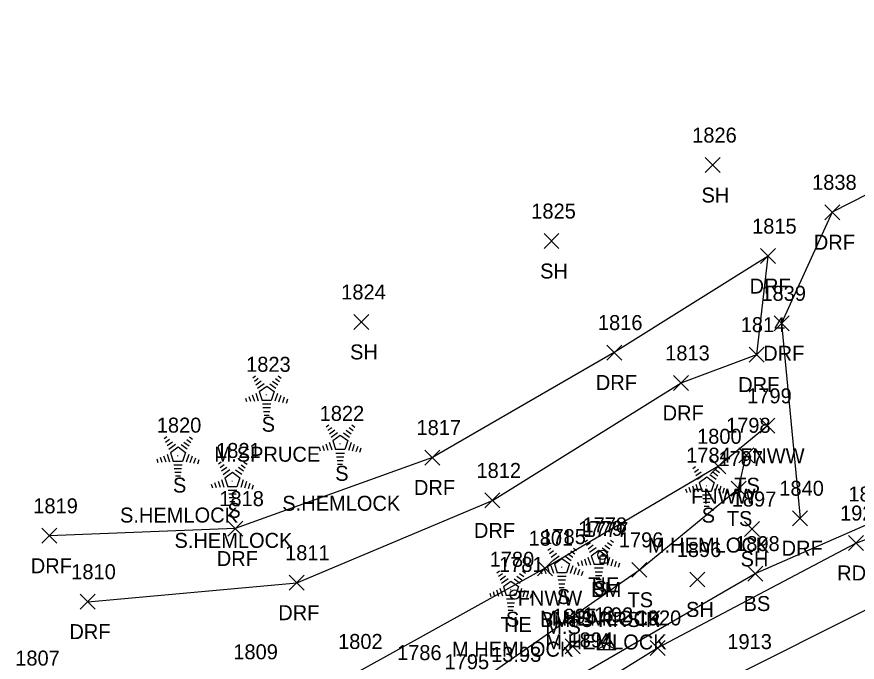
# Model space of a CAD drawing. Extents: x 1621633 to 1624015, y 417863 to 420979.
# Drawn here: x 1621653.9 to 1621766.2, y 418036.6 to 418122.7 of the extents above; entities that cross this region are included whole.
import ezdxf

# ---------------------------------------------------------------- set-up
doc = ezdxf.new("R2010")
doc.units = 0
for name, color, linetype in [('C_A', 7, 'Continuous'), ('C_C', 7, 'Continuous'), ('C_I', 7, 'Continuous'), ('CBP', 7, 'Continuous'), ('CPBM', 7, 'Continuous'), ('CPSM', 7, 'Continuous'), ('L_A', 7, 'Continuous'), ('L_C', 7, 'Continuous'), ('L_I', 7, 'Continuous'), ('L_TIC', 7, 'Continuous'), ('LELB', 7, 'Continuous'), ('LFNC', 7, 'Continuous'), ('LTC', 7, 'Continuous'), ('P_A', 7, 'Continuous'), ('P_I', 7, 'Continuous'), ('P_TIC', 7, 'Continuous'), ('PEU', 7, 'Continuous'), ('PRC', 7, 'Continuous'), ('R_A', 7, 'Continuous'), ('R_I', 7, 'Continuous'), ('R_TIC', 7, 'Continuous'), ('RDF', 7, 'Continuous')]:
    doc.layers.add(name, color=color, linetype=linetype)

msp = doc.modelspace()

# ---------------------------------------------------------------- linework, layer by layer
at = {"layer": 'CBP'}
for centre, radius in [((1621732.16, 418050.87), 0.625), ((1621732.16, 418050.87), 0.0833), ((1621720.46, 418045.6), 0.625), ((1621720.46, 418045.6), 0.0833)]:
    msp.add_circle(centre, radius, dxfattribs=at)
at = {"layer": 'CPBM'}
for p, q in [((1621731.83, 418049.75), (1621731.83, 418050.75)), ((1621731.83, 418050.75), (1621732.83, 418050.75)), ((1621732.83, 418050.75), (1621732.83, 418049.75)), ((1621732.83, 418049.75), (1621731.83, 418049.75)), ((1621732.33, 418050.25), (1621732.33, 418050.25)), ((1621732.33, 418050.25), (1621732.33, 418050.25))]:
    msp.add_line(p, q, dxfattribs=at)
at = {"layer": 'CPSM'}
for p, q in [((1621731.45, 418038.24), (1621732.7, 418040.4)), ((1621733.95, 418038.24), (1621732.7, 418040.4)), ((1621732.7, 418038.96), (1621732.7, 418040.4)), ((1621731.45, 418038.24), (1621732.7, 418038.96)), ((1621731.45, 418038.24), (1621733.95, 418038.24)), ((1621732.7, 418038.96), (1621732.7, 418038.96)), ((1621732.7, 418038.96), (1621733.95, 418038.24))]:
    msp.add_line(p, q, dxfattribs=at)
at = {"layer": 'L_TIC'}
for points in [[(1621745.88, 418101.9), (1621747.88, 418103.9)], [(1621747.88, 418101.9), (1621745.88, 418103.9)], [(1621724.34, 418091.76), (1621726.34, 418093.76)], [(1621726.34, 418091.76), (1621724.34, 418093.76)], [(1621698.95, 418080.96), (1621700.95, 418082.96)], [(1621700.95, 418080.96), (1621698.95, 418082.96)], [(1621753.17, 418067.1), (1621755.17, 418069.1)], [(1621755.17, 418067.1), (1621753.17, 418069.1)], [(1621750.34, 418063.17), (1621752.34, 418065.17)], [(1621752.34, 418063.17), (1621750.34, 418065.17)], [(1621746.63, 418061.7), (1621748.63, 418063.7)], [(1621748.63, 418061.7), (1621746.63, 418063.7)], [(1621749.33, 418058.72), (1621751.33, 418060.72)], [(1621751.33, 418058.72), (1621749.33, 418060.72)], [(1621751.11, 418053.33), (1621753.11, 418055.33)], [(1621753.11, 418053.33), (1621751.11, 418055.33)], [(1621723.49, 418048.1), (1621725.49, 418050.1)], [(1621725.49, 418048.1), (1621723.49, 418050.1)], [(1621736.08, 418047.88), (1621738.08, 418049.88)], [(1621738.08, 418047.88), (1621736.08, 418049.88)], [(1621751.55, 418047.38), (1621753.55, 418049.38)], [(1621753.55, 418047.38), (1621751.55, 418049.38)], [(1621743.81, 418046.59), (1621745.81, 418048.59)], [(1621745.81, 418046.59), (1621743.81, 418048.59)], [(1621727.15, 418037.69), (1621729.15, 418039.69)], [(1621729.15, 418037.69), (1621727.15, 418039.69)]]:
    msp.add_lwpolyline(points, dxfattribs=at)
at = {"layer": 'LELB'}
for points in [[(1621664.03, 417989.43), (1621687.49, 418007.66), (1621711.94, 418024.27), (1621730.31, 418035.53), (1621752.55, 418048.38), (1621767.69, 418055), (1621798.3, 418066.25), (1621826.91, 418075.93), (1621858.25, 418085.3), (1621888.98, 418092.53), (1621914.26, 418098.41), (1621931, 418100.47)], [(1621661.36, 417992.68), (1621685.31, 418010.41), (1621692.18, 418016.19), (1621713.76, 418032.62), (1621737.08, 418048.88), (1621750.33, 418059.72), (1621751.34, 418064.17)]]:
    msp.add_lwpolyline(points, dxfattribs=at)
at = {"layer": 'LFNC'}
msp.add_lwpolyline([(1621754.17, 418068.1), (1621747.63, 418062.7), (1621724.49, 418049.1), (1621699.62, 418035.32), (1621679.62, 418023.17), (1621653.98, 418003.68)], dxfattribs=at)
at = {"layer": 'LTC'}
for p, q in [((1621685.45, 418074.52), (1621685.8, 418074.78)), ((1621685.66, 418074.06), (1621686.19, 418074.44)), ((1621685.87, 418073.59), (1621686.57, 418074.1)), ((1621688.1, 418074.07), (1621688.78, 418073.57)), ((1621688.47, 418074.41), (1621689.02, 418074.02)), ((1621688.85, 418074.76), (1621689.26, 418074.46)), ((1621686.08, 418073.13), (1621686.95, 418073.76)), ((1621686.3, 418072.67), (1621687.31, 418073.41)), ((1621687.31, 418073.41), (1621688.31, 418072.68)), ((1621687.73, 418073.72), (1621688.54, 418073.13)), ((1621684.48, 418071.8), (1621684.63, 418071.33)), ((1621684.94, 418072.02), (1621685.15, 418071.37)), ((1621685.39, 418072.24), (1621685.66, 418071.4)), ((1621685.85, 418072.45), (1621686.18, 418071.43)), ((1621686.3, 418072.67), (1621686.69, 418071.48)), ((1621688.31, 418072.68), (1621687.92, 418071.48)), ((1621688.75, 418072.41), (1621688.41, 418071.37)), ((1621689.19, 418072.16), (1621688.9, 418071.27)), ((1621689.64, 418071.91), (1621689.4, 418071.18)), ((1621687.92, 418071.48), (1621686.69, 418071.48)), ((1621687.88, 418070.98), (1621686.74, 418070.98)), ((1621690.08, 418071.66), (1621689.89, 418071.08)), ((1621687.8, 418070.48), (1621686.81, 418070.48)), ((1621687.71, 418069.98), (1621686.88, 418069.98)), ((1621687.63, 418069.48), (1621686.95, 418069.48)), ((1621695.27, 418067.97), (1621695.62, 418068.23)), ((1621695.48, 418067.5), (1621696.01, 418067.89)), ((1621695.69, 418067.04), (1621696.39, 418067.55)), ((1621695.9, 418066.57), (1621696.78, 418067.21)), ((1621697.92, 418067.51), (1621698.6, 418067.02)), ((1621698.3, 418067.86), (1621698.85, 418067.46)), ((1621698.67, 418068.21), (1621699.09, 418067.91)), ((1621673.6, 418066.4), (1621673.96, 418066.66)), ((1621673.81, 418065.94), (1621674.34, 418066.32)), ((1621676.63, 418066.29), (1621677.18, 418065.89)), ((1621677, 418066.64), (1621677.42, 418066.34)), ((1621696.12, 418066.12), (1621697.13, 418066.85)), ((1621696.12, 418066.12), (1621696.51, 418064.92)), ((1621697.13, 418066.85), (1621698.13, 418066.13)), ((1621697.55, 418067.17), (1621698.36, 418066.58)), ((1621698.13, 418066.13), (1621697.74, 418064.92)), ((1621674.02, 418065.47), (1621674.72, 418065.98)), ((1621674.23, 418065), (1621675.11, 418065.64)), ((1621674.45, 418064.55), (1621675.47, 418065.28)), ((1621675.47, 418065.28), (1621676.46, 418064.56)), ((1621675.89, 418065.6), (1621676.7, 418065.01)), ((1621676.26, 418065.94), (1621676.94, 418065.45)), ((1621694.3, 418065.25), (1621694.45, 418064.78)), ((1621694.76, 418065.47), (1621694.97, 418064.81)), ((1621695.21, 418065.68), (1621695.48, 418064.85)), ((1621695.67, 418065.9), (1621696, 418064.88)), ((1621698.57, 418065.86), (1621698.23, 418064.82)), ((1621699.01, 418065.61), (1621698.73, 418064.72)), ((1621699.46, 418065.36), (1621699.22, 418064.63)), ((1621699.9, 418065.11), (1621699.71, 418064.53)), ((1621673.09, 418063.9), (1621673.3, 418063.25)), ((1621673.54, 418064.11), (1621673.82, 418063.28)), ((1621674, 418064.33), (1621674.33, 418063.31)), ((1621674.45, 418064.55), (1621674.84, 418063.36)), ((1621676.46, 418064.56), (1621676.07, 418063.36)), ((1621676.9, 418064.29), (1621676.56, 418063.25)), ((1621677.34, 418064.04), (1621677.06, 418063.15)), ((1621697.74, 418064.92), (1621696.51, 418064.92)), ((1621697.7, 418064.42), (1621696.56, 418064.42)), ((1621697.62, 418063.92), (1621696.63, 418063.92)), ((1621672.63, 418063.68), (1621672.79, 418063.21)), ((1621676.07, 418063.36), (1621674.84, 418063.36)), ((1621676.03, 418062.86), (1621674.89, 418062.86)), ((1621677.79, 418063.79), (1621677.55, 418063.06)), ((1621678.23, 418063.54), (1621678.05, 418062.96)), ((1621680.87, 418063.02), (1621681.23, 418063.28)), ((1621681.08, 418062.55), (1621681.61, 418062.94)), ((1621683.9, 418062.91), (1621684.45, 418062.51)), ((1621684.27, 418063.26), (1621684.69, 418062.96)), ((1621697.53, 418063.42), (1621696.7, 418063.42)), ((1621697.45, 418062.92), (1621696.77, 418062.92)), ((1621675.95, 418062.36), (1621674.96, 418062.36)), ((1621675.87, 418061.86), (1621675.03, 418061.86)), ((1621681.29, 418062.09), (1621682, 418062.6)), ((1621681.5, 418061.62), (1621682.38, 418062.26)), ((1621681.73, 418061.17), (1621682.74, 418061.9)), ((1621682.74, 418061.9), (1621683.74, 418061.18)), ((1621683.16, 418062.22), (1621683.97, 418061.63)), ((1621683.53, 418062.56), (1621684.21, 418062.07)), ((1621744.21, 418062.39), (1621744.57, 418062.65)), ((1621744.42, 418061.93), (1621744.95, 418062.31)), ((1621744.63, 418061.46), (1621745.34, 418061.97)), ((1621744.84, 418061), (1621745.72, 418061.63)), ((1621746.87, 418061.94), (1621747.55, 418061.44)), ((1621747.24, 418062.28), (1621747.79, 418061.89)), ((1621747.61, 418062.63), (1621748.03, 418062.33)), ((1621675.78, 418061.36), (1621675.11, 418061.36)), ((1621680.36, 418060.52), (1621680.57, 418059.86)), ((1621680.82, 418060.73), (1621681.09, 418059.9)), ((1621681.27, 418060.95), (1621681.6, 418059.93)), ((1621681.73, 418061.17), (1621682.11, 418059.97)), ((1621683.74, 418061.18), (1621683.34, 418059.97)), ((1621684.17, 418060.91), (1621683.84, 418059.87)), ((1621684.62, 418060.66), (1621684.33, 418059.77)), ((1621745.07, 418060.54), (1621746.08, 418061.28)), ((1621745.07, 418060.54), (1621745.45, 418059.35)), ((1621746.08, 418061.28), (1621747.08, 418060.55)), ((1621746.5, 418061.59), (1621747.31, 418061)), ((1621747.08, 418060.55), (1621746.68, 418059.35)), ((1621679.91, 418060.3), (1621680.06, 418059.83)), ((1621683.34, 418059.97), (1621682.11, 418059.97)), ((1621683.31, 418059.47), (1621682.16, 418059.47)), ((1621685.06, 418060.41), (1621684.83, 418059.68)), ((1621685.51, 418060.16), (1621685.32, 418059.58)), ((1621743.25, 418059.67), (1621743.4, 418059.2)), ((1621743.7, 418059.89), (1621743.91, 418059.24)), ((1621744.16, 418060.11), (1621744.43, 418059.27)), ((1621744.61, 418060.32), (1621744.94, 418059.3)), ((1621746.68, 418059.35), (1621745.45, 418059.35)), ((1621747.51, 418060.28), (1621747.17, 418059.24)), ((1621747.96, 418060.03), (1621747.67, 418059.14)), ((1621748.4, 418059.78), (1621748.16, 418059.05)), ((1621748.85, 418059.53), (1621748.66, 418058.95)), ((1621683.22, 418058.97), (1621682.23, 418058.97)), ((1621683.14, 418058.47), (1621682.31, 418058.47)), ((1621746.65, 418058.85), (1621745.5, 418058.85)), ((1621746.56, 418058.35), (1621745.57, 418058.35)), ((1621683.06, 418057.97), (1621682.38, 418057.97)), ((1621746.48, 418057.85), (1621745.65, 418057.85)), ((1621746.39, 418057.35), (1621745.72, 418057.35)), ((1621729.8, 418052.62), (1621730.16, 418052.88)), ((1621733.2, 418052.86), (1621733.62, 418052.56)), ((1621724.87, 418051.52), (1621725.23, 418051.78)), ((1621728.27, 418051.76), (1621728.69, 418051.46)), ((1621730.01, 418052.16), (1621730.54, 418052.54)), ((1621730.22, 418051.69), (1621730.92, 418052.2)), ((1621730.43, 418051.22), (1621731.31, 418051.86)), ((1621730.65, 418050.77), (1621731.67, 418051.5)), ((1621731.67, 418051.5), (1621732.66, 418050.78)), ((1621732.09, 418051.82), (1621732.9, 418051.23)), ((1621732.46, 418052.16), (1621733.14, 418051.67)), ((1621732.83, 418052.51), (1621733.38, 418052.11)), ((1621725.08, 418051.06), (1621725.61, 418051.44)), ((1621725.29, 418050.59), (1621726, 418051.1)), ((1621725.5, 418050.12), (1621726.38, 418050.76)), ((1621725.73, 418049.67), (1621726.74, 418050.4)), ((1621726.74, 418050.4), (1621727.73, 418049.68)), ((1621727.16, 418050.72), (1621727.97, 418050.13)), ((1621727.53, 418051.06), (1621728.21, 418050.57)), ((1621727.9, 418051.41), (1621728.45, 418051.01)), ((1621730.2, 418050.55), (1621730.53, 418049.53)), ((1621730.65, 418050.77), (1621731.04, 418049.58)), ((1621732.66, 418050.78), (1621732.27, 418049.58)), ((1621733.1, 418050.51), (1621732.76, 418049.47)), ((1621725.27, 418049.45), (1621725.6, 418048.43)), ((1621725.73, 418049.67), (1621726.11, 418048.48)), ((1621727.73, 418049.68), (1621727.34, 418048.48)), ((1621728.17, 418049.41), (1621727.83, 418048.37)), ((1621728.83, 418049.9), (1621728.99, 418049.43)), ((1621729.29, 418050.12), (1621729.5, 418049.47)), ((1621729.74, 418050.33), (1621730.02, 418049.5)), ((1621732.27, 418049.58), (1621731.04, 418049.58)), ((1621733.55, 418050.26), (1621733.26, 418049.37)), ((1621733.99, 418050.01), (1621733.75, 418049.28)), ((1621734.43, 418049.76), (1621734.25, 418049.18)), ((1621718.05, 418048.49), (1621718.41, 418048.75)), ((1621718.26, 418048.03), (1621718.79, 418048.41)), ((1621721.08, 418048.39), (1621721.63, 418047.99)), ((1621721.45, 418048.73), (1621721.87, 418048.43)), ((1621723.9, 418048.8), (1621724.06, 418048.33)), ((1621724.36, 418049.02), (1621724.57, 418048.37)), ((1621724.82, 418049.23), (1621725.09, 418048.4)), ((1621727.34, 418048.48), (1621726.11, 418048.48)), ((1621728.62, 418049.16), (1621728.33, 418048.27)), ((1621729.06, 418048.91), (1621728.82, 418048.18)), ((1621729.51, 418048.66), (1621729.32, 418048.08)), ((1621732.23, 418049.08), (1621731.09, 418049.08)), ((1621732.15, 418048.58), (1621731.16, 418048.58)), ((1621718.47, 418047.56), (1621719.18, 418048.07)), ((1621718.68, 418047.1), (1621719.56, 418047.74)), ((1621718.91, 418046.64), (1621719.92, 418047.38)), ((1621719.92, 418047.38), (1621720.92, 418046.65)), ((1621720.34, 418047.69), (1621721.15, 418047.1)), ((1621720.71, 418048.04), (1621721.39, 418047.54)), ((1621727.3, 418047.98), (1621726.16, 418047.98)), ((1621727.22, 418047.48), (1621726.23, 418047.48)), ((1621732.07, 418048.08), (1621731.23, 418048.08)), ((1621731.98, 418047.58), (1621731.31, 418047.58)), ((1621717.54, 418045.99), (1621717.75, 418045.34)), ((1621718, 418046.21), (1621718.27, 418045.37)), ((1621718.45, 418046.42), (1621718.78, 418045.4)), ((1621718.91, 418046.64), (1621719.3, 418045.45)), ((1621720.92, 418046.65), (1621720.53, 418045.45)), ((1621721.35, 418046.38), (1621721.02, 418045.34)), ((1621721.8, 418046.13), (1621721.51, 418045.25)), ((1621722.24, 418045.88), (1621722.01, 418045.15)), ((1621727.14, 418046.98), (1621726.31, 418046.98)), ((1621727.05, 418046.48), (1621726.38, 418046.48)), ((1621717.09, 418045.77), (1621717.24, 418045.31)), ((1621720.53, 418045.45), (1621719.3, 418045.45)), ((1621720.49, 418044.95), (1621719.34, 418044.95)), ((1621722.69, 418045.63), (1621722.5, 418045.06)), ((1621720.4, 418044.45), (1621719.42, 418044.45)), ((1621720.32, 418043.95), (1621719.49, 418043.95)), ((1621720.24, 418043.45), (1621719.56, 418043.45))]:
    msp.add_line(p, q, dxfattribs=at)
at = {"layer": 'P_TIC'}
for points in [[(1621765, 418051.46), (1621767, 418053.46)], [(1621767, 418051.46), (1621765, 418053.46)], [(1621738.5, 418037.46), (1621740.5, 418039.46)], [(1621740.5, 418037.46), (1621738.5, 418039.46)]]:
    msp.add_lwpolyline(points, dxfattribs=at)
at = {"layer": 'PEU'}
msp.add_lwpolyline([(1621666.09, 417987.33), (1621690.6, 418006.33), (1621714.11, 418022.73), (1621739.5, 418038.46), (1621766, 418052.46), (1621797.99, 418064.45), (1621829.1, 418075.2), (1621862.24, 418084.7), (1621894.03, 418092.42)], dxfattribs=at)
at = {"layer": 'PRC'}
msp.add_lwpolyline([(1621971.07, 418099.34), (1621938.44, 418093.73), (1621906.63, 418086.95), (1621874.87, 418079.94), (1621842.52, 418071.19), (1621811.53, 418061.42), (1621780.51, 418050.11), (1621750.95, 418035.3), (1621723.04, 418018.53), (1621696.18, 418000.53), (1621670.93, 417981.57)], dxfattribs=at)
at = {"layer": 'R_TIC'}
for points in [[(1621761.83, 418095.6), (1621763.83, 418097.6)], [(1621763.83, 418095.6), (1621761.83, 418097.6)], [(1621753.26, 418089.75), (1621755.26, 418091.75)], [(1621755.26, 418089.75), (1621753.26, 418091.75)], [(1621755.07, 418080.78), (1621757.07, 418082.78)], [(1621757.07, 418080.78), (1621755.07, 418082.78)], [(1621732.72, 418076.88), (1621734.72, 418078.88)], [(1621734.72, 418076.88), (1621732.72, 418078.88)], [(1621751.74, 418076.6), (1621753.74, 418078.6)], [(1621753.74, 418076.6), (1621751.74, 418078.6)], [(1621741.64, 418072.82), (1621743.64, 418074.82)], [(1621743.64, 418072.82), (1621741.64, 418074.82)], [(1621708.44, 418062.87), (1621710.44, 418064.87)], [(1621710.44, 418062.87), (1621708.44, 418064.87)], [(1621716.44, 418057.14), (1621718.44, 418059.14)], [(1621718.44, 418057.14), (1621716.44, 418059.14)], [(1621757.54, 418054.77), (1621759.54, 418056.77)], [(1621759.54, 418054.77), (1621757.54, 418056.77)], [(1621682.1, 418053.38), (1621684.1, 418055.38)], [(1621684.1, 418053.38), (1621682.1, 418055.38)], [(1621657.27, 418052.42), (1621659.27, 418054.42)], [(1621659.27, 418052.42), (1621657.27, 418054.42)], [(1621690.32, 418046.16), (1621692.32, 418048.16)], [(1621692.32, 418046.16), (1621690.32, 418048.16)], [(1621662.42, 418043.63), (1621664.42, 418045.63)], [(1621664.42, 418043.63), (1621662.42, 418045.63)]]:
    msp.add_lwpolyline(points, dxfattribs=at)
at = {"layer": 'RDF'}
for points in [[(1621940.59, 418295.72), (1621925.73, 418267.99), (1621914.41, 418239.65), (1621902.22, 418210.53), (1621883.89, 418186.91), (1621861.02, 418166.16), (1621838.61, 418146.11), (1621813.95, 418127.94), (1621789.4, 418110.13), (1621762.83, 418096.6), (1621756.07, 418081.78), (1621758.54, 418055.77)], [(1621663.42, 418044.63), (1621691.32, 418047.16), (1621717.44, 418058.14), (1621742.64, 418073.82), (1621752.74, 418077.6), (1621754.26, 418090.75), (1621733.72, 418077.88), (1621709.44, 418063.87), (1621683.1, 418054.38), (1621658.27, 418053.42)]]:
    msp.add_lwpolyline(points, dxfattribs=at)

# ---------------------------------------------------------------- texts
at = {"layer": 'C_A'}
for s, p in [('TIE', (1621730.24, 418045.87)), ('BM', (1621730.64, 418045.25)), ('TIE', (1621718.54, 418040.6))]:
    msp.add_text(s, height=2, dxfattribs=at).set_placement(p)
at = {"layer": 'C_C'}
for s, p in [('11.92', (1621729.55, 418041.87)), ('BM#3 RRSIR', (1621723.83, 418041.25)), ('M.HEMLOCK', (1621724.52, 418038.25)), ('13.93', (1621717.28, 418036.6))]:
    msp.add_text(s, height=2, dxfattribs=at).set_placement(p)
at = {"layer": 'C_I'}
for s, p in [('1778', (1621729.47, 418053.87)), ('1777', (1621729.63, 418053.25)), ('1781', (1621718.33, 418048.6)), ('8', (1621732.14, 418041.96))]:
    msp.add_text(s, height=2, dxfattribs=at).set_placement(p)
at = {"layer": 'L_A'}
for s, p in [('SH', (1621745.37, 418097.9)), ('SH', (1621723.82, 418087.76)), ('SH', (1621698.44, 418076.96)), ('S', (1621686.64, 418067.31)), ('FNWW', (1621750.52, 418063.1)), ('S', (1621696.46, 418060.76)), ('S', (1621674.79, 418059.19)), ('TS', (1621749.75, 418059.17)), ('FNWW', (1621743.98, 418057.7)), ('S', (1621682.06, 418055.81)), ('S', (1621745.4, 418055.18)), ('TS', (1621748.74, 418054.72)), ('SH', (1621750.59, 418049.33)), ('S', (1621730.99, 418045.41)), ('FNWW', (1621720.83, 418044.1)), ('S', (1621726.06, 418044.31)), ('TS', (1621735.49, 418043.88)), ('BS', (1621750.99, 418043.38)), ('SH', (1621743.3, 418042.59)), ('S', (1621719.25, 418041.29))]:
    msp.add_text(s, height=2, dxfattribs=at).set_placement(p)
at = {"layer": 'L_C'}
for s, p in [('M.SPRUCE', (1621680.34, 418063.31)), ('S.HEMLOCK', (1621689.39, 418056.76)), ('S.HEMLOCK', (1621667.72, 418055.19)), ('S.HEMLOCK', (1621674.99, 418051.81)), ('M.HEMLOCK', (1621738.21, 418051.18)), ('M.HEMLOCK', (1621723.8, 418041.41)), ('M.S', (1621724.5, 418040.31)), ('M.HEMLOCK', (1621712.05, 418037.29))]:
    msp.add_text(s, height=2, dxfattribs=at).set_placement(p)
at = {"layer": 'L_I'}
for s, p in [('1826', (1621744.13, 418105.9)), ('1825', (1621722.64, 418095.76)), ('1824', (1621697.26, 418084.96)), ('1823', (1621684.56, 418075.31)), ('1799', (1621751.47, 418071.1)), ('1822', (1621694.38, 418068.76)), ('1820', (1621672.63, 418067.19)), ('1798', (1621748.65, 418067.17)), ('1800', (1621744.78, 418065.7)), ('1821', (1621680.55, 418063.81)), ('1784', (1621743.32, 418063.18)), ('1797', (1621747.64, 418062.72)), ('1897', (1621749.41, 418057.33)), ('1899', (1621764.99, 418058)), ('1779', (1621728.91, 418053.41)), ('1801', (1621722.28, 418052.1)), ('1785', (1621723.98, 418052.31)), ('1796', (1621734.33, 418051.88)), ('1896', (1621742.06, 418050.59)), ('1898', (1621749.86, 418051.38)), ('1780', (1621717.08, 418049.29)), ('1895', (1621725.45, 418041.69)), ('1802', (1621696.84, 418038.32)), ('1894', (1621727.61, 418038.53)), ('1807', (1621653.73, 418036.1)), ('1809', (1621682.85, 418036.94)), ('1786', (1621704.71, 418036.83)), ('1795', (1621711.06, 418035.62))]:
    msp.add_text(s, height=2, dxfattribs=at).set_placement(p)
at = {"layer": 'LTC'}
for p in [(1621687.19, 418072.42), (1621697.02, 418065.87), (1621675.35, 418064.3), (1621682.62, 418060.92), (1621745.96, 418060.29), (1621731.55, 418050.52), (1621726.62, 418049.42), (1621719.8, 418046.39)]:
    msp.add_text('.', height=1.04, rotation=270, dxfattribs=at).set_placement(p)
at = {"layer": 'P_A'}
msp.add_text('RDG', height=2, dxfattribs=at).set_placement((1621763.49, 418047.46))
at = {"layer": 'P_I'}
for s, p in [('1921', (1621763.87, 418055.46)), ('1920', (1621736.72, 418041.46)), ('1913', (1621748.82, 418038.3))]:
    msp.add_text(s, height=2, dxfattribs=at).set_placement(p)
at = {"layer": 'R_A'}
for p in [(1621760.37, 418091.6), (1621751.79, 418085.75), (1621753.61, 418076.78), (1621731.26, 418072.88), (1621750.27, 418072.6), (1621740.18, 418068.82), (1621706.97, 418058.87), (1621714.98, 418053.14), (1621756.07, 418050.77), (1621655.8, 418048.42), (1621680.64, 418049.38), (1621688.85, 418042.16), (1621660.96, 418039.63)]:
    msp.add_text('DRF', height=2, dxfattribs=at).set_placement(p)
at = {"layer": 'R_I'}
for s, p in [('1838', (1621760.14, 418099.6)), ('1815', (1621752.13, 418093.75)), ('1839', (1621753.37, 418084.78)), ('1816', (1621731.54, 418080.88)), ('1814', (1621750.61, 418080.6)), ('1813', (1621740.52, 418076.82)), ('1817', (1621707.31, 418066.87)), ('1812', (1621715.32, 418061.14)), ('1840', (1621755.76, 418058.77)), ('1818', (1621680.98, 418057.38)), ('1819', (1621656.14, 418056.42)), ('1811', (1621689.76, 418050.16)), ('1810', (1621661.21, 418047.63))]:
    msp.add_text(s, height=2, dxfattribs=at).set_placement(p)

doc.saveas('drawing.dxf')
